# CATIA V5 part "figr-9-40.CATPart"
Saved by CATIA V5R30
Part number: Part1
Bounding box of the stored display mesh (mm): x -40 to 40, y -20 to 191.034, z 0 to 131.919
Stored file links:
  D:\PROJECTS\CATIA V56R 2020\Resources\Parts File\c09_catia_v5_6r2020_prt\figr-9-40.CATPart
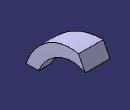
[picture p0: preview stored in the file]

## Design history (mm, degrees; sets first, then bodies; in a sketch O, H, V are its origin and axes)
Set1
  Plane1: type Normal, Curve Sketch2, RefPoint vertex of Sketch2
Body1 (main body)
  Sketch1 on xy-plane, origin (0, 0, 0), H (1, 0, 0), V (0, 1, 0)
    line L1 (20, 20) -> (20, -20)
    line L2 (20, -20) -> (-20, -20)
    line L3 (-20, -20) -> (-20, 20)
    line L4 (-20, 20) -> (20, 20)
    vertical: L1 V, L3 V
    horizontal: L2 H, L4 H
    equidistance: L1 L3 O, L2 L4 O
  Sketch2 on yz-plane, origin (0, 0, 0), H (0, 1, 0), V (0, 0, 1)
    spline S1 through (0, 0) (20, 60) (60, 80) (120, 90) (180, 110)
    point P1 (0, 0)
    coincidence: P1 O
  Sketch3 on Plane1, origin (0, 186.3865, 97.8327), H (1, 0, 0), V (0, -0.4648, 0.8854)
    point P1 (0, 13.7415)
    line L1 (40, 37.4831) -> (40, -10)
    line L2 (40, -10) -> (-40, -10)
    line L3 (-40, -10) -> (-40, 37.4831)
    line L4 (-40, 37.4831) -> (40, 37.4831)
    reference projected point E1 (0, 13.7415) from vertex of Sketch2
    coincidence: P1 V, P1 E1
    vertical: L1 V, L3 V
    horizontal: L2 H, L4 H
    equidistance: L1 L3 P1, L2 L4 P1
  Loft1: Sections (Sketch1; Sketch3)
